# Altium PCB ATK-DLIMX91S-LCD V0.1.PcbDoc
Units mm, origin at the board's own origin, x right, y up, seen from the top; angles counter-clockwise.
Board outline 43.25 x 70.25 mm, 2 copper layers (Top Layer, Bottom Layer), stack 1.495 mm thick; 16 components, 39 nets, 110 pads, 307 vias.
Unrouted connection lines stored in the file: 5.
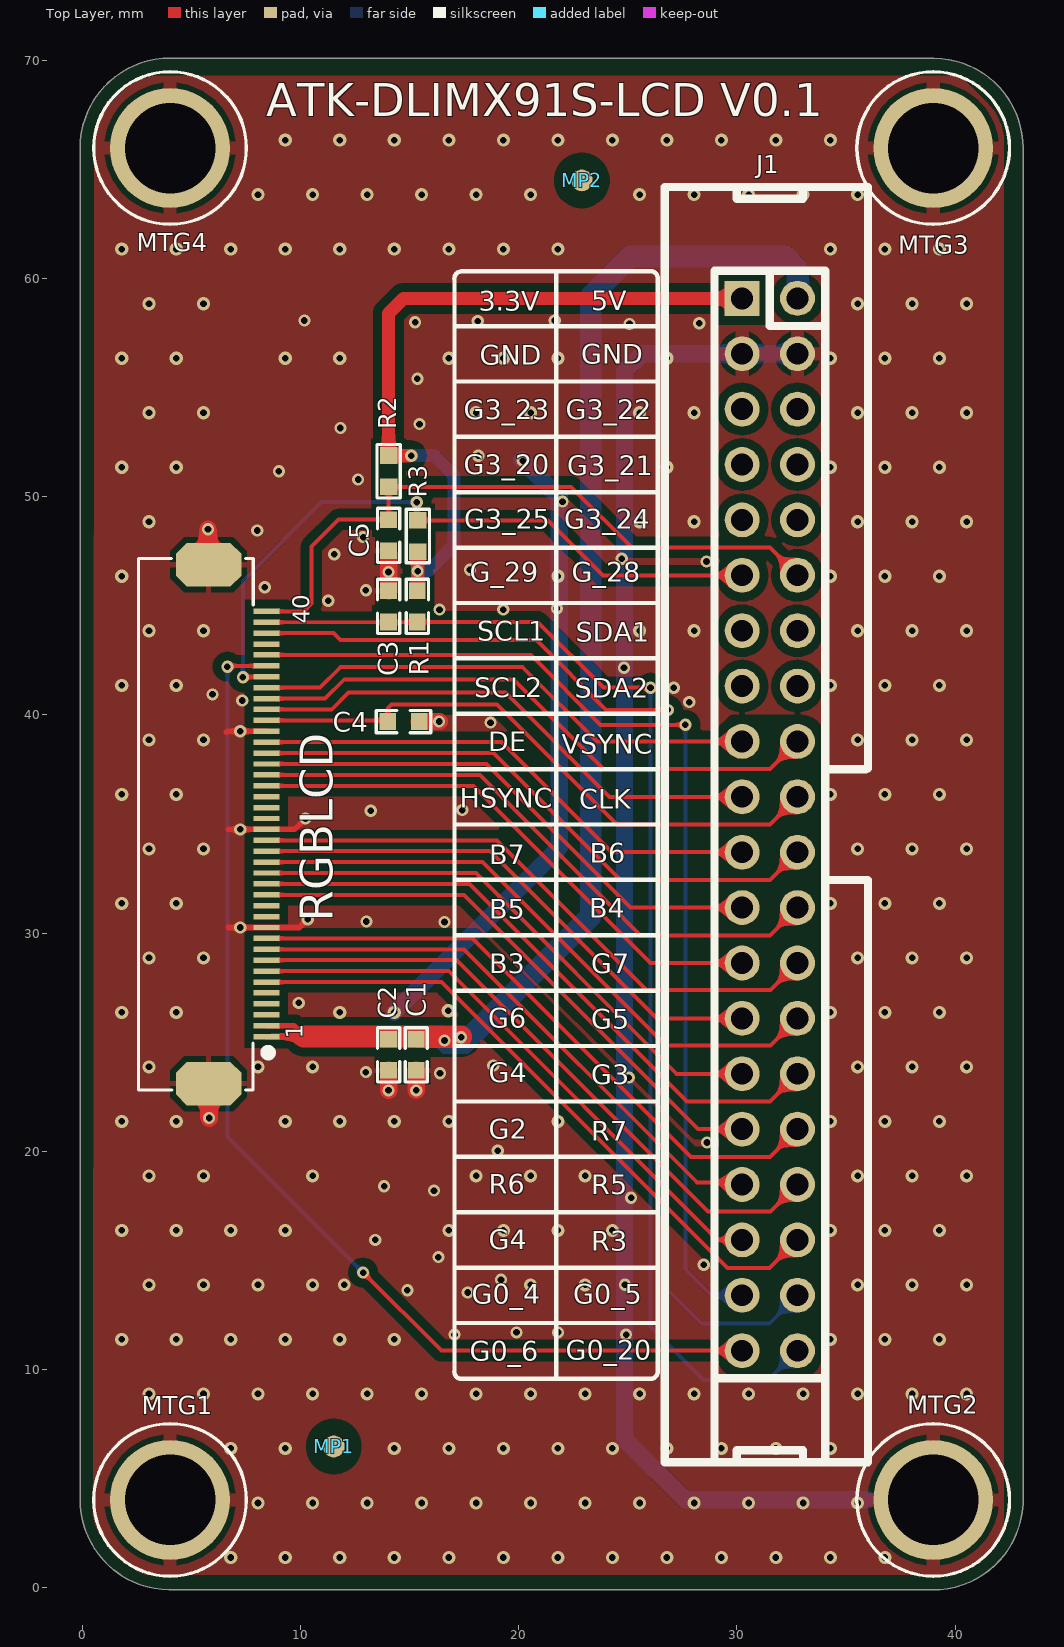
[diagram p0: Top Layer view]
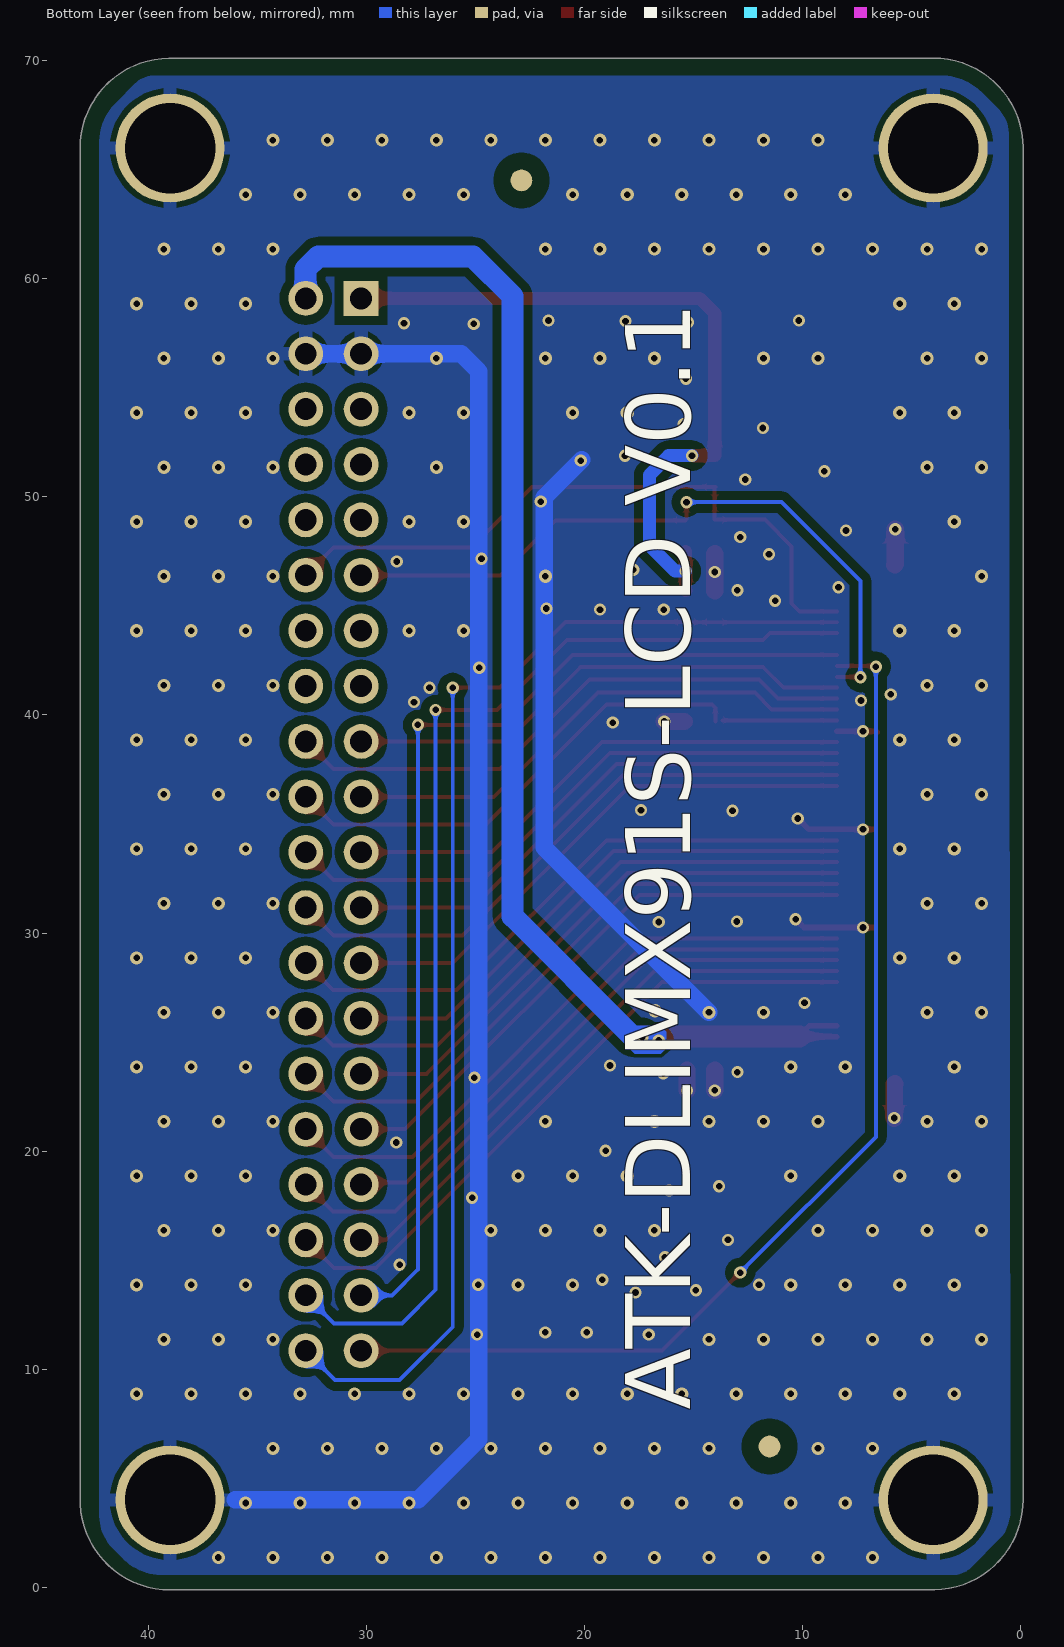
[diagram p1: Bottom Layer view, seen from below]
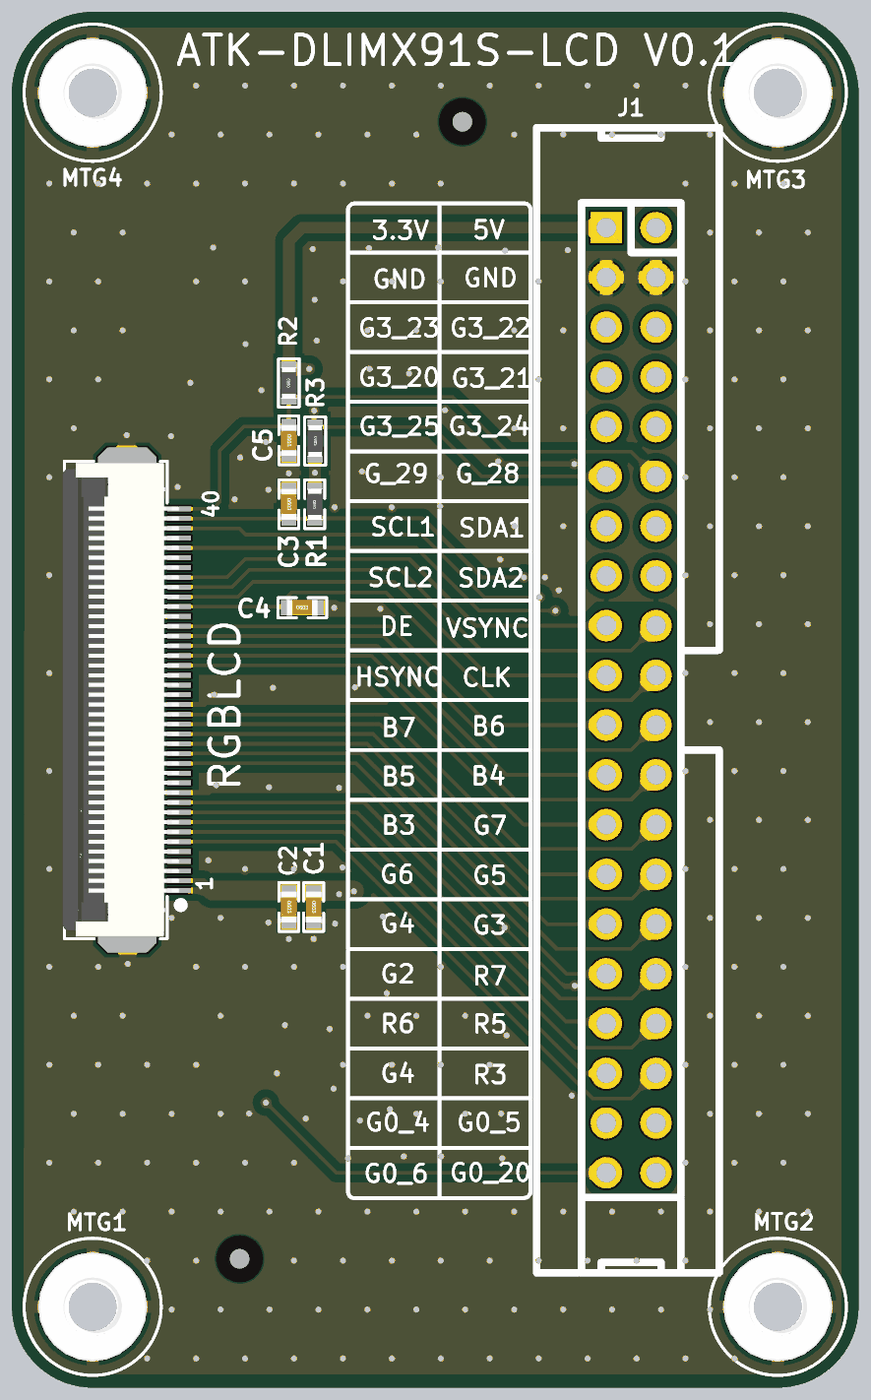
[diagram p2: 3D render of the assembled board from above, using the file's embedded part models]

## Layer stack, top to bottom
Top Solder: solder mask 0.0102, Solder Resist, Dk 3.5
Top Layer: signal copper 0.0175
Dielectric 2: prepreg 0.13, PP-006, Dk 4.1
Dielectric 1: dielectric 1.2, FR-4, Dk 4.8
Dielectric 3: prepreg 0.13, PP-006, Dk 4.1
Bottom Layer: signal copper 0.0175
Bottom Solder: solder mask 0.0102, Solder Resist, Dk 3.5

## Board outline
-0.123,4.022 ccw(c4.004,4.004) 3.954,-0.123 3.988,-0.127 38.946,-0.127 38.978,-0.123 ccw(c38.996,4.004) 43.118,3.797 43.127,3.846 43.127,65.946 43.123,65.996 ccw(c38.996,65.996) 39.046,70.123 39.012,70.127 4,70.127 ccw(c4,66) -0.127,66.02 -0.127,66.016

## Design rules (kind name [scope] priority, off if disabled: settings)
BoardOutlineClearance [All] p1: gap=0.508 ignorepadtopadclearanceinfootprint=FALSE
Clearance [All] p1: gap=0.152 ignorepadtopadclearanceinfootprint=FALSE except(0.14: Arc-Arc Arc-Track Arc-SMDPad Track-SMDPad SMDPad-SMDPad; 0.203: Arc-Fill Track-Fill SMDPad-Fill THPad-Fill Via-Fill; 0.216: Track-Track; 0.381: Fill-Fill; 0.4: Arc-Poly Track-Poly SMDPad-Poly THPad-Poly Via-Poly Fill-Poly Poly-Poly)
DiffPairsRouting [InDifferentialPair('MIC')] p1: maxlimit=0.254 minlimit=0.254 mostfreqgap=0.254 toplayer_minwidth=0.254 toplayer_maxwidth=0.381 toplayer_prefwidth=0.254 bottomlayer_minwidth=0.254 bottomlayer_maxwidth=0.381 bottomlayer_prefwidth=0.254 maxuncoupledlength=12.7
DiffPairsRouting 90OHM [InDifferentialPairClass('90OHM')] p2: maxlimit=0.178 minlimit=0.178 mostfreqgap=0.178 toplayer_minwidth=0.178 toplayer_maxwidth=0.178 toplayer_prefwidth=0.178 bottomlayer_minwidth=0.178 bottomlayer_maxwidth=0.178 bottomlayer_prefwidth=0.178 maxuncoupledlength=12.7
DiffPairsRouting 100OHM [InDifferentialPairClass('100OHM')] p3: maxlimit=0.198 minlimit=0.14 mostfreqgap=0.14 toplayer_maxgap=0.14 toplayer_minwidth=0.127 toplayer_maxwidth=0.127 toplayer_prefwidth=0.127 bottomlayer_minwidth=0.127 bottomlayer_maxwidth=0.127 bottomlayer_prefwidth=0.127 maxuncoupledlength=12.7
PlaneClearance [All] p1: clearance=0.203
PlaneConnect [All] p1: planeconnectstyle=Direct reliefexpansion=0.508 reliefentries=4 reliefconductorwidth=0.508 reliefairgap=0.254
PolygonConnect [All] p1: thpad.connectstyle=Relief thpad.reliefconductorwidth=0.635 thpad.reliefentries=4 thpad.polygonreliefangle="90 Angle" thpad.airgapwidth=0.254 smdpad.connectstyle=Relief smdpad.reliefconductorwidth=0.254 smdpad.reliefentries=4 smdpad.polygonreliefangle="90 Angle" smdpad.airgapwidth=0.254 via.connectstyle=Direct via.reliefconductorwidth=0.254 via.reliefentries=4 via.polygonreliefangle="90 Angle" via.airgapwidth=0.254
RoutingVias [All] p1: holewidth=0.254 width=0.508 viastyle="Through Hole" minholewidth=0.203 minwidth=0.406 maxholewidth=2 maxwidth=2
SilkToSilkClearance [All] p1: silktosilkclearance=0.051
SilkToSolderMaskClearance [IsPad] p1: minsilkscreentomaskgap=0.051 clearancetoexposedcopper=TRUE
SolderMaskExpansion [All] p1: expansion=0.102 istentingtop=FALSE
Width 50OHM [InNetClass('50OHM')] p1: maxlimit=0.254 minlimit=0.183 preferedwidth=0.183 minimp=50.000000 maximp=50.000000 favimp=50.000000
Width [All] p2: maxlimit=2.54 minlimit=0.152 preferedwidth=0.183
25 further rules are at their usual default settings.

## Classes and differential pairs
net class RGB_LCD: GPIO3_IO22
net class GMAC: GPIO3_IO20 GPIO3_IO25 GPIO_IO01 GPIO_IO28 GPIO_IO29
net class 50OHM: GPIO3_IO20 GPIO3_IO25 GPIO_IO28 GPIO_IO29
differential pair class 90OHM: D_CPU_USB0 D_CPU_USB1 D_HUB1 D_HUB2 D_HUB3 D_HUB4 USB_OTG USB_TTL
differential pair class 100OHM: D_PHY0_RJ45_D1 D_PHY0_RJ45_D2 D_PHY0_RJ45_D3 D_PHY0_RJ45_D4 D_PHY1_RJ45_D1 D_PHY1_RJ45_D2 D_PHY1_RJ45_D3 D_PHY1_RJ45_D4
differential pair MIC: +"" -""
differential pair USB_TTL: +I2C2_SCL -I2C1_SDA
differential pair USB_OTG: +"" -""
differential pair D_CPU_USB0: +"" -""
differential pair D_CPU_USB1: +"" -""
differential pair D_HUB2: +"" -""
differential pair D_HUB1: +"" -""
differential pair D_HUB3: +"" -""
differential pair D_HUB4: +"" -""
differential pair D_PHY0_RJ45_D1: +"" -""
differential pair D_PHY0_RJ45_D2: +"" -""
differential pair D_PHY0_RJ45_D3: +"" -""
differential pair D_PHY0_RJ45_D4: +"" -""
differential pair D_PHY1_RJ45_D1: +"" -""
differential pair D_PHY1_RJ45_D2: +"" -""
differential pair D_PHY1_RJ45_D3: +"" -""
differential pair D_PHY1_RJ45_D4: +"" -""

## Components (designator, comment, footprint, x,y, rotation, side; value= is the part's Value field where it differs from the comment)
C1 "10uF" "C 0603" 15.291,24.416 r270 top
C2 "100nF" "C 0603" 14.021,24.416 r270 top
C3 "1nF" "C 0603" 14.021,44.983 r270 top
C4 "22pF" "C 0603" 14.707,39.7 r0 top
C5 "10uF" "C 0603" 14.021,48.241 r270 top
J1 "40Pin" "IDC 2.54-2*20P" 30.237,59.106 r270 top
MP1 "Mark Point" "MARK POINT" 11.506,6.452 r90 top
MP2 "Mark Point" "MARK POINT" 22.885,64.516 r90 top
MTG1 "MTG_Hole" M3-6ET 4,4 r0 top
MTG2 "MTG_Hole" M3-6ET 39,4 r0 top
MTG3 "MTG_Hole" M3-6ET 39,66 r0 top
MTG4 "MTG_Hole" M3-6ET 4,66 r0 top
R1 "10K" "R 0603"#1 15.342,44.983 r90 top
R2 "10K" "R 0603"#2 14.021,51.181 r90 top
R3 "10K" "R 0603"#2 15.367,48.209 r270 top
RGBLCD "RGBLCD" FPC0.5-TOP40P 7.095,34.99 r90 top

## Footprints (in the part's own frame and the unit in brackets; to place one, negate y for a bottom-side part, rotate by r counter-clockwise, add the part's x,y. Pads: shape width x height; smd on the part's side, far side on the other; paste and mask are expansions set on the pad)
"C 0603" [mil] "无极性贴片电容"
  rect 30x30 smd mask+2: 1(-28.25,0) 2(28.25,0)
  silkscreen extent -49,-20 49,20, body extent -31,-16 32,16, height 32
FPC0.5-TOP40P [mm] "FPCTOP;0.5mm;"
  rect 0.25x1.2 smd: 1(-9.737,-1.326) 2(-9.237,-1.326) 3(-8.737,-1.326) 4(-8.237,-1.326) 5(-7.737,-1.326) 6(-7.237,-1.326) 7(-6.737,-1.326) 8(-6.237,-1.326) 9(-5.737,-1.326) 10(-5.237,-1.326) 11(-4.737,-1.326) 12(-4.237,-1.326) 13(-3.737,-1.326) 14(-3.237,-1.326) 15(-2.737,-1.326) 16(-2.237,-1.326) 17(-1.737,-1.326) 18(-1.237,-1.326) 19(-0.737,-1.326) 20(-0.237,-1.326) 21(0.263,-1.326) 22(0.763,-1.326) 23(1.263,-1.326) 24(1.763,-1.326) 25(2.263,-1.326) 26(2.763,-1.326) 27(3.263,-1.326) 28(3.763,-1.326) 29(4.263,-1.326) 30(4.763,-1.326) 31(5.263,-1.326) 32(5.763,-1.326) 33(6.263,-1.326) 34(6.763,-1.326) 35(7.263,-1.326) 36(7.763,-1.326) 37(8.263,-1.326) 38(8.763,-1.326) 39(9.263,-1.326) 40(9.763,-1.326)
  oct 2x3 smd: A(-11.9,1.326) B(11.9,1.326)
  silkscreen extent -12.19,-1.58 12.19,4.54, body extent -12.08,-1.35 12.12,4.65, height 2
"IDC 2.54-2*20P" [mm]
  rect 1.6x1.6 hole 1: 1(0,0)
  round 1.6 hole 1: 2(0,2.54) 3(2.54,0) 4(2.54,2.54) 5(5.08,0) 6(5.08,2.54) 7(7.62,0) 8(7.62,2.54) 9(10.16,0) 10(10.16,2.54) 11(12.7,0) 12(12.7,2.54) 13(15.24,0) 14(15.24,2.54) 15(17.78,0) 16(17.78,2.54) 17(20.32,0) 18(20.32,2.54) 19(22.86,0) 20(22.86,2.54) 21(25.4,0) 22(25.4,2.54) 23(27.94,0) 24(27.94,2.54) 25(30.48,0) 26(30.48,2.54) 27(33.02,0) 28(33.02,2.54) 29(35.56,0) 30(35.56,2.54) 31(38.1,0) 32(38.1,2.54) 33(40.64,0) 34(40.64,2.54) 35(43.18,0) 36(43.18,2.54) 37(45.72,0) 38(45.72,2.54) 39(48.26,0) 40(48.26,2.54)
  silkscreen extent -5.11,-3.56 53.37,5.77
M3-6ET [mm]
  round 5.5 / inner round 5 / far side round 5 hole 4.15 mask+0.051: 1(0,0)
  silkscreen extent -3.5,-3.5 3.5,3.5, body extent -2.77,-2.78 2.77,2.78, height 6.03
"MARK POINT" [mm]
  round 1 smd: 1(0,0)
  round 2.4 on Top Solder paste+0 mask+0.01: 1(0,0)
  round 2.4 on Bottom Solder paste+0 mask+0.01: 1(0,0)
  round 1 smd far side: 1_1(0,0)
  Top Layer pour cut-out: -1.27,0.125 -1.221,0.37 -1.125,0.602 -0.986,0.81 -0.81,0.986 -0.602,1.125 -0.37,1.221 -0.125,1.27 0,1.27 0.125,1.27 0.37,1.221 0.602,1.125 0.81,0.986 0.986,0.81 1.125,0.602 1.221,0.37 1.27,0.125 1.27,0 1.27,0 1.27,-0.125 1.221,-0.37 1.125,-0.602 0.986,-0.81 0.81,-0.986 0.602,-1.125 0.37,-1.221 0.125,-1.27 0,-1.27 0,-1.27 -0.125,-1.27 -0.37,-1.221 -0.602,-1.125 -0.81,-0.986 -0.986,-0.81 -1.125,-0.602 -1.221,-0.37 -1.27,-0.125 -1.27,0
  Bottom Layer pour cut-out: -1.27,0 -1.27,0.125 -1.221,0.37 -1.125,0.602 -0.986,0.81 -0.81,0.986 -0.602,1.125 -0.37,1.221 -0.125,1.27 0,1.27 0,1.27 0.125,1.27 0.37,1.221 0.602,1.125 0.81,0.986 0.986,0.81 1.125,0.602 1.221,0.37 1.27,0.125 1.27,0 1.27,0 1.27,-0.125 1.221,-0.37 1.125,-0.602 0.986,-0.81 0.81,-0.986 0.602,-1.125 0.37,-1.221 0.125,-1.27 0,-1.27 0,-1.27 -0.125,-1.27 -0.37,-1.221 -0.602,-1.125 -0.81,-0.986 -0.986,-0.81 -1.125,-0.602 -1.221,-0.37 -1.27,-0.125 -1.27,0
"R 0603"#1 [mil] "1/10W贴片电阻"
  rect 30x30 smd mask+2: 1(-28.25,0) 2(28.25,0)
  silkscreen extent -49,-20 49,20, body extent -32,-16 31,16, height 16
"R 0603"#2 [mil] "1/10W贴片电阻"
  rect 30x31.5 smd mask+2: 1(-28.25,0) 2(28.25,0)
  silkscreen extent -48,-21 48,21, body extent -32,-16 31,16, height 16

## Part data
C1 C2 C3 C4 C5: library part C, "无极性贴片电容"
J1: library part RPI40Pin
MP1 MP2: library part MARK
MTG1 MTG2 MTG3 MTG4: "螺丝孔"
R1 R2 R3: library part R
RGBLCD: library part FPC-40, "FPC-40P-0.5mm"

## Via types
v1: diameter 0.6, hole 0.3, Top Layer to Bottom Layer, tented both sides, 227 vias
v2: diameter 0.559, hole 0.305, Top Layer to Bottom Layer, tented both sides, 80 vias

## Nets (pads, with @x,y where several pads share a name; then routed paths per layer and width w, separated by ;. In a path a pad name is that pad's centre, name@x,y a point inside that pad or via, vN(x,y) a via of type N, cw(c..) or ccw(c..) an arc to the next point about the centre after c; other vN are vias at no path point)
GND: C1.2 C2.2 C3.1 C4.2 C5.2 J1.3 J1.4 MTG1.1 MTG2.1 MTG3.1 MTG4.1 RGBLCD.11 RGBLCD.20 RGBLCD.29 RGBLCD.A RGBLCD.B | length 115.8
  Top Layer w0.254: 6.579,39.218 cw(c6.663,39.133) 6.663,39.253 RGBLCD.29 ; 6.663,30.253 RGBLCD.11 9.933,30.253 v2(10.312,30.632) ; 6.663,34.753 RGBLCD.20 9.708,34.753 v2(10.211,35.255)
  Top Layer w0.8: v2(5.74,48.514) 5.74,46.918 RGBLCD.B ; RGBLCD.A 5.791,23.068 v2(5.791,21.514) ; v2(14.021,22.784) C2.2 ; C3.1 C5.2@14.021,47.39 ; v2(15.291,22.784) C1.2 ; C4.2 v2(16.339,39.7)
  Bottom Layer w0.8: v1(14.284,26.361) 21.844,33.921 21.844,44.882 21.844,46.361 21.844,49.987 v2@20.125,51.706 ; J1.4 25.654,56.566 24.841,55.753 24.841,6.782 27.623,4 36,4
  other v1: 6.784,1.361 9.284,1.361 11.784,1.361 14.284,1.361 16.784,1.361 19.284,1.361 21.784,1.361 24.284,1.361 26.784,1.361 29.284,1.361 31.784,1.361 34.284,1.361 36.784,1.361 8.034,3.861 10.534,3.861 13.034,3.861 15.534,3.861 18.034,3.861 20.534,3.861 23.034,3.861 25.534,3.861 28.034,3.861 30.534,3.861 33.034,3.861 35.534,3.861 6.784,6.361 9.284,6.361 14.284,6.361 16.784,6.361 19.284,6.361 21.784,6.361 24.284,6.361 26.784,6.361 29.284,6.361 31.784,6.361 34.284,6.361 3.034,8.861 5.534,8.861 8.034,8.861 10.534,8.861 13.034,8.861 15.534,8.861 18.034,8.861 20.534,8.861 23.034,8.861 25.534,8.861 28.034,8.861 30.534,8.861 33.034,8.861 35.534,8.861 38.034,8.861 40.534,8.861 1.784,11.361 4.284,11.361 6.784,11.361 9.284,11.361 11.784,11.361 14.284,11.361 34.284,11.361 36.784,11.361 39.284,11.361 3.034,13.861 5.534,13.861 8.034,13.861 10.534,13.861 20.534,13.861 23.034,13.861 35.534,13.861 38.034,13.861 40.534,13.861 1.784,16.361 4.284,16.361 6.784,16.361 9.284,16.361 16.784,16.361 19.284,16.361 21.784,16.361 24.284,16.361 34.284,16.361 36.784,16.361 39.284,16.361 3.034,18.861 5.534,18.861 10.534,18.861 18.034,18.861 20.534,18.861 23.034,18.861 35.534,18.861 38.034,18.861 40.534,18.861 1.784,21.361 4.284,21.361 9.284,21.361 11.784,21.361 14.284,21.361 16.784,21.361 21.784,21.361 34.284,21.361 36.784,21.361 39.284,21.361 3.034,23.861 8.034,23.861 10.534,23.861 35.534,23.861 38.034,23.861 40.534,23.861 1.784,26.361 4.284,26.361 11.784,26.361 34.284,26.361 36.784,26.361 39.284,26.361 16.76,26.436 3.034,28.861 5.534,28.861 35.534,28.861 38.034,28.861 40.534,28.861 1.784,31.361 4.284,31.361 34.284,31.361 36.784,31.361 39.284,31.361 3.034,33.861 5.534,33.861 35.534,33.861 38.034,33.861 40.534,33.861 1.784,36.361 4.284,36.361 34.284,36.361 36.784,36.361 39.284,36.361 3.034,38.861 5.534,38.861 35.534,38.861 38.034,38.861 40.534,38.861 1.784,41.361 4.284,41.361 34.284,41.361 36.784,41.361 39.284,41.361 3.034,43.861 5.534,43.861 25.534,43.861 28.034,43.861 35.534,43.861 38.034,43.861 40.534,43.861 1.784,46.361 21.784,46.361 34.284,46.361 36.784,46.361 39.284,46.361 3.034,48.861 25.534,48.861 28.034,48.861 35.534,48.861 38.034,48.861 40.534,48.861 1.784,51.361 4.284,51.361 26.784,51.361 34.284,51.361 36.784,51.361 39.284,51.361 3.034,53.861 5.534,53.861 18.034,53.861 20.534,53.861 25.534,53.861 28.034,53.861 35.534,53.861 38.034,53.861 40.534,53.861 1.784,56.361 4.284,56.361 9.284,56.361 11.784,56.361 16.784,56.361 19.284,56.361 21.784,56.361 26.784,56.361 34.284,56.361 36.784,56.361 39.284,56.361 3.034,58.861 5.534,58.861 35.534,58.861 38.034,58.861 40.534,58.861 1.784,61.361 4.284,61.361 6.784,61.361 9.284,61.361 11.784,61.361 14.284,61.361 16.784,61.361 19.284,61.361 21.784,61.361 34.284,61.361 36.784,61.361 39.284,61.361 8.034,63.861 10.534,63.861 13.034,63.861 15.534,63.861 18.034,63.861 20.534,63.861 25.534,63.861 28.034,63.861 30.534,63.861 33.034,63.861 35.534,63.861 9.284,66.361 11.784,66.361 14.284,66.361 16.784,66.361 19.284,66.361 21.784,66.361 24.284,66.361 26.784,66.361 29.284,66.361 31.784,66.361 34.284,66.361
  other v2: 17.043,11.582 24.917,11.582 19.888,11.684 21.793,11.684 17.653,13.513 14.884,13.614 11.989,13.868 24.867,13.868 19.177,14.097 28.473,14.783 16.307,15.138 13.411,15.926 25.146,17.856 16.104,18.186 13.818,18.39 19.025,20.015 28.626,20.396 25.044,23.368 16.383,23.571 12.979,23.622 18.821,23.927 9.906,26.797 7.219,30.253 16.586,30.505 13.005,30.531 7.219,34.753 13.208,35.611 17.399,35.636 7.219,39.253 18.694,39.649 27.813,40.589 7.315,40.665 5.944,40.945 27.102,41.25 24.816,42.164 16.358,44.831 19.279,44.831 21.742,44.882 11.252,45.237 12.979,45.72 8.342,45.861 14.021,46.558 17.755,46.66 28.6,47.041 24.714,47.168 11.532,47.371 12.852,48.158 8.001,48.463 21.996,49.784 12.624,50.8 8.992,51.181 20.168,51.664 18.136,51.892 11.811,53.162 15.443,53.34 15.342,55.423 25.07,57.937 28.27,57.963 15.24,58.014 18.11,58.064 10.16,58.09 21.641,58.09
GPIO3_IO20: J1.7
GPIO3_IO21: J1.8
GPIO3_IO22: J1.6
GPIO3_IO23: J1.5
GPIO3_IO24: J1.10
GPIO3_IO25: J1.9
GPIO_IO00: C4.1 J1.20 RGBLCD.30 | length 27.5
  Top Layer w0.183: RGBLCD.30 C4.1@13.66,39.753 ; C4.1 13.989,40.329 14.148,40.488 18.991,40.488 24.503,34.976 31.507,34.976 J1.20
GPIO_IO01: J1.17 RGBLCD.33 | length 23.6
  Top Layer w0.183: RGBLCD.33 10.874,41.253 11.811,42.189 20.168,42.189 23.571,38.786 J1.17
GPIO_IO02: J1.18 RGBLCD.32 | length 26.9
  Top Layer w0.183: RGBLCD.32 11.111,40.753 11.989,41.631 19.761,41.631 23.876,37.516 31.507,37.516 J1.18
GPIO_IO03: J1.19 RGBLCD.31 | length 24.1
  Top Layer w0.183: RGBLCD.31 11.415,40.253 12.184,41.021 19.38,41.021 24.155,36.246 J1.19
GPIO_IO04: J1.37 RGBLCD.36 | length 48.6
  Top Layer w0.183: RGBLCD.36 20.544,42.753 23.749,39.548 v2(27.635,39.548)
  Bottom Layer w0.183: v2(27.635,39.548) 27.635,14.58 28.829,13.386 J1.37
GPIO_IO05: J1.38 RGBLCD.38 | length 53.6
  Top Layer w0.183: RGBLCD.38 11.492,43.753 11.811,43.434 20.803,43.434 24.003,40.234 v2(26.822,40.234)
  Bottom Layer w0.183: v2(26.822,40.234) 26.822,13.64 28.372,12.09 31.481,12.09 J1.38
GPIO_IO06: J1.39 RGBLCD.35 | length 51
  Top Layer w0.183: v2(6.629,42.215) 6.667,42.253 RGBLCD.35 ; v2@12.852,14.44 16.447,10.846 J1.39
  Bottom Layer w0.183: v2(6.629,42.215) 6.629,20.65 v2(12.852,14.427)
GPIO_IO07: J1.36 RGBLCD.6 | length 30.3
  Top Layer w0.183: RGBLCD.6 16.443,27.753 29.566,14.63 31.481,14.63 J1.36
GPIO_IO08: J1.35 RGBLCD.7 | length 26.9
  Top Layer w0.183: RGBLCD.7 16.782,28.253 29.108,15.926 J1.35
GPIO_IO09: J1.34 RGBLCD.8 | length 29.6
  Top Layer w0.183: RGBLCD.8 17.145,28.753 28.677,17.221 31.532,17.221 J1.34
GPIO_IO10: J1.33 RGBLCD.9 | length 26.3
  Top Layer w0.183: RGBLCD.9 17.483,29.253 28.167,18.569 30.133,18.569 J1.33
GPIO_IO11: J1.32 RGBLCD.10 | length 29
  Top Layer w0.183: RGBLCD.10 17.872,29.753 27.889,19.736 31.507,19.736 J1.32
GPIO_IO14: J1.31 RGBLCD.14 | length 26.3
  Top Layer w0.183: RGBLCD.14 17.473,31.753 28.219,21.006 J1.31
GPIO_IO15: J1.30 RGBLCD.15 | length 29
  Top Layer w0.183: RGBLCD.15 17.735,32.253 27.711,22.276 31.507,22.276 J1.30
GPIO_IO16: J1.29 RGBLCD.16 | length 25.6
  Top Layer w0.183: RGBLCD.16 18.022,32.753 27.229,23.546 J1.29
GPIO_IO17: J1.28 RGBLCD.17 | length 28.4
  Top Layer w0.183: RGBLCD.17 18.335,33.253 26.746,24.841 31.532,24.841 J1.28
GPIO_IO18: J1.27 RGBLCD.18 | length 25
  Top Layer w0.183: RGBLCD.18 18.673,33.753 26.34,26.086 J1.27
GPIO_IO19: J1.26 RGBLCD.19 | length 27.7
  Top Layer w0.183: RGBLCD.19 18.986,34.253 25.857,27.381 31.532,27.381 J1.26
GPIO_IO20: C3.2 J1.40 R1.1 RGBLCD.39 | length 56.5
  Top Layer w0.183: RGBLCD.39 14.046,44.253 15.328,44.253 R1.1 20.86,44.266 23.876,41.25 v2(26.035,41.25)
  Bottom Layer w0.183: v2(26.035,41.25) 26.035,11.938 28.473,9.5 31.431,9.5 J1.40
GPIO_IO23: J1.25 RGBLCD.24 | length 25.2
  Top Layer w0.183: RGBLCD.24 17.908,36.753 26.035,28.626 J1.25
GPIO_IO24: J1.24 RGBLCD.25 | length 27.9
  Top Layer w0.183: RGBLCD.25 18.221,37.253 25.578,29.896 31.507,29.896 J1.24
GPIO_IO25: J1.23 RGBLCD.26 | length 24.5
  Top Layer w0.183: RGBLCD.26 18.521,37.753 25.108,31.166 J1.23
GPIO_IO26: J1.22 RGBLCD.27 | length 27.3
  Top Layer w0.183: RGBLCD.27 18.834,38.253 24.651,32.436 31.507,32.436 J1.22
GPIO_IO27: J1.21 RGBLCD.28 | length 23.9
  Top Layer w0.183: RGBLCD.28 19.198,38.753 24.245,33.706 J1.21
GPIO_IO28: C5.1 J1.12 R2.1 RGBLCD.40 | length 30.9
  Top Layer w0.183: RGBLCD.40 10.132,44.753 10.49,45.11 10.49,47.727 11.722,48.959 C5.1 14.021,50.438 13.995,50.463 22.397,50.463 25.185,47.676 31.507,47.676 J1.12
GPIO_IO29: J1.11 R3.1 RGBLCD.34 | length 31.7
  Top Layer w0.183: v2(7.341,41.729) 7.352,41.741 8.41,41.741 RGBLCD.34 ; v2(15.316,49.759) 15.316,48.978 R3.1 21.33,48.927 23.851,46.406 J1.11
  Bottom Layer w0.183: v2(7.341,41.729) 7.341,46.152 10.947,49.759 v2(15.316,49.759)
I2C1_SCL: J1.13
I2C1_SDA: J1.14
I2C2_SCL: J1.15
I2C2_SDA: J1.16
VCC_3V3: J1.1 R1.2 R2.2 R3.2 | length 33.6
  Top Layer w0.6: v2(15.062,51.892) 14.027,51.892 R2.2 14.021,58.415 14.711,59.106 J1.1 ; R1.2 15.354,45.714 v2(15.354,46.596) 15.354,47.479 R3.2
  Bottom Layer w0.6: v2(15.062,51.892) 16.129,51.892 17.018,51.003 17.018,47.777 15.837,46.596 v2(15.354,46.596)
VCC_5V: C1.1 C2.1 J1.2 RGBLCD.1 RGBLCD.2 | length 61.4
  Top Layer w0.254: RGBLCD.1 10.129,25.253 10.129,25.304 9.68,25.753 RGBLCD.2
  Top Layer w1: 10.129,25.253 14.021,25.253 15.291,25.253 v2@17.348,25.253 ; C1.1@15.381,25.223 v2(17.348,25.222)
  Bottom Layer w1: v2(17.348,25.222) 17.755,25.222 23.292,30.759 23.292,59.207 25.11,61.026 32.206,61.026 32.791,60.44 32.791,59.12 J1.2
  other v2: 16.586,25.07
pads on no net: MP1.1 MP1.1_1 MP2.1 MP2.1_1 RGBLCD.3 RGBLCD.4 RGBLCD.5 RGBLCD.12 RGBLCD.13 RGBLCD.21 RGBLCD.22 RGBLCD.23 RGBLCD.37

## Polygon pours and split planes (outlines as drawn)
GND on Bottom Layer "GND_L02_P000" (solid, remove dead copper, pour order 0): 0.478,4.717 ccw(c0.521,4.675) 0.46,4.675 0.46,3.319 ccw(c1.884,3.319) 0.877,2.312 2.357,0.832 ccw(c3.017,1.492) 3.017,0.559 39.357,0.559 ccw(c39.357,3.099) 41.153,1.303 41.6,1.749 ccw(c40.053,3.295) 42.24,3.295 42.24,66.258 ccw(c39.7,66.258) 41.496,68.054 40.589,68.961 ccw(c39.731,68.103) 39.731,69.317 3.592,69.317 ccw(c3.592,66.777) 1.796,68.573 1.041,67.818 ccw(c2.268,66.592) 0.533,66.592 0.533,62.763
GND on Top Layer "GND_L01_P001" (solid, remove dead copper, pour order 1): 0.478,4.717 ccw(c0.521,4.675) 0.46,4.675 0.46,3.319 ccw(c1.884,3.319) 0.877,2.312 2.357,0.832 ccw(c3.017,1.492) 3.017,0.559 39.357,0.559 ccw(c39.357,3.099) 41.153,1.303 41.6,1.749 ccw(c40.053,3.295) 42.24,3.295 42.24,66.258 ccw(c39.7,66.258) 41.496,68.054 40.589,68.961 ccw(c39.731,68.103) 39.731,69.317 3.592,69.317 ccw(c3.592,66.777) 1.796,68.573 1.041,67.818 ccw(c2.268,66.592) 0.533,66.592 0.533,62.763

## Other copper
Top Layer:
  pour cut-out: 28.956,39.192 cw(c29.14,39.192) 29.01,39.322 29.616,39.929 cw(c29.8,39.745) 29.8,40.005 32.898,40.005 cw(c32.898,38.791) 33.757,39.649 cw(c33.511,39.404) 33.858,39.404 33.858,10.494 cw(c32.991,10.494) 33.604,9.881 cw(c33.052,10.432) 33.052,9.652 29.965,9.652 cw(c29.965,10.432) 29.413,9.881 cw(c30.088,10.555) 29.134,10.555 29.134,38.437 ccw(c28.353,38.437) 28.905,38.989
Bottom Layer:
  region net VCC_5V: 18.275,25.754 18.274,25.756 16.524,25.756 16.245,25.476 16.245,24.714 16.499,24.46 17.692,24.46 18.378,25.146 18.378,25.656 18.277,25.756

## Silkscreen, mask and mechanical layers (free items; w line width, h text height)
Top Overlay:
  lines w0.2: 17.043,9.838 17.043,19.472 17.043,19.726 17.043,60.053 ; 17.043,12.116 26.365,12.116 ; 17.043,14.656 26.365,14.656 ; 17.043,17.196 26.365,17.196 ; 17.043,19.736 26.365,19.736 ; 17.043,22.276 26.365,22.276 ; 17.043,24.816 26.365,24.816 ; 17.043,27.356 26.365,27.356 ; 17.043,29.896 26.365,29.896 ; 17.043,32.436 26.365,32.436 ; 17.043,34.976 26.365,34.976 ; 17.043,37.516 26.365,37.516 ; 17.043,40.056 26.365,40.056 ; 17.043,42.596 26.365,42.596 ; 17.043,45.136 26.365,45.136 ; 17.043,47.676 26.365,47.676 ; 17.043,50.216 26.365,50.216 ; 17.043,52.756 26.365,52.756 ; 17.043,55.296 26.365,55.296 ; 17.043,57.836 26.365,57.836 ; 17.348,9.56 26.06,9.56 ; 17.348,60.35 26.06,60.35 ; 21.717,9.627 21.717,60.325 ; 26.365,9.848 26.365,19.482 26.365,19.736 ; 26.365,60.063 26.365,19.736
  lines w0.203: 17.042,9.881 ccw(c17.362,9.871) 17.348,9.55 ; 17.042,60.01 cw(c17.362,60.02) 17.348,60.34 ; 26.06,9.561 ccw(c26.046,9.881) 26.367,9.891 ; 26.06,60.35 cw(c26.046,60.03) 26.367,60.02
  text "ATK-DLIMX91S-LCD V0.1" at 8.414,67.449 h1.5
  text "5V" at 23.315,58.57 h0.9
  text "3.3V" at 18.159,58.545 h0.9
  text "GND" at 22.857,56.114 h0.9
  text "GND" at 18.207,56.051 h0.9
  text "G3_23" at 17.473,53.561 h0.9
  text "G3_22" at 22.146,53.559 h0.9
  text "G3_20" at 17.473,51.047 h0.9
  text "G3_21" at 22.22,50.996 h0.9
  text "G3_25" at 17.493,48.545 h0.9
  text "G3_24" at 22.07,48.545 h0.9
  text "G_29" at 17.752,46.119 h0.9
  text "G_28" at 22.426,46.119 h0.9
  text "SCL1" at 18.09,43.394 h0.9
  text "SDA1" at 22.604,43.355 h0.9
  text "SCL2" at 17.955,40.813 h0.9
  text "SDA2" at 22.553,40.79 h0.9
  text "DE" at 18.583,38.326 h0.9
  text "VSYNC" at 21.956,38.232 h0.9
  text "HSYNC" at 17.295,35.735 h0.9
  text "CLK" at 22.774,35.71 h0.9
  text "B6" at 23.251,33.231 h0.9
  text "B7" at 18.649,33.158 h0.9
  text "B4" at 23.226,30.691 h0.9
  text "B5" at 18.649,30.658 h0.9
  text "B3" at 18.649,28.166 h0.9
  text "G7" at 23.317,28.154 h0.9
  text "G6" at 18.583,25.659 h0.9
  text "G5" at 23.309,25.601 h0.9
  text "G4" at 18.605,23.145 h0.9
  text "G3" at 23.309,23.061 h0.9
  text "G2" at 18.606,20.572 h0.9
  text "R7" at 23.309,20.468 h0.9
  text "R6" at 18.606,18.032 h0.9
  text "R5" at 23.32,18.009 h0.9
  text "G4" at 18.606,15.492 h0.9
  text "R3" at 23.32,15.426 h0.9
  text "G0_4" at 17.828,12.998 h0.9
  text "G0_5" at 22.502,12.998 h0.9
  text "G0_20" at 22.146,10.432 h0.9
  text "G0_6" at 17.752,10.381 h0.9
Bottom Overlay:
  text "ATK-DLIMX91S-LCD V0.1" at 15.137,8.142 h3 r270
Drill Guide:
  lines w0.254: 0,1.651 0,0 1.651,0
Mechanical 1:
  lines w0.254: 0,4.054 0,66.016 cw(c4,66) 4.05,70 ; 0.005,4.054 ccw(c4.004,4.004) 3.988,0.004 ; 3.988,0 38.946,0 ; 4,70 39.012,70 ; 38.946,0.005 ccw(c38.996,4.004) 42.996,3.988 ; 39.012,69.996 cw(c38.996,65.996) 42.995,65.946 ; 43,3.846 43,65.946
Mechanical 3:
  lines w0.013: 61.642,12.626 61.642,41.27 ; 64.792,9.426 98.542,9.426 ; 64.892,44.426 98.642,44.426 ; 101.642,12.626 101.642,41.312
Mechanical 6:
  circle w0.013: c62.03,11.426 r1.1
  circle w0.013: c62.03,42.426 r1.1
  circle w0.013: c98.03,42.426 r1.1
  circle w0.013: c98.03,11.426 r1.1
  lines w0.013: 60.03,11.426 ccw(c62.03,11.426) 62.03,9.426 98.03,9.426 ccw(c98.03,11.426) 100.03,11.426 100.03,42.426 ccw(c98.03,42.426) 98.03,44.426 62.03,44.426 ccw(c62.03,42.426) 60.03,42.426 60.03,11.426
Mechanical 14:
  circle w0.013: c85.05,10.868 r0.125
  circle w0.013: c77.591,40.307 r0.076
  circle w0.013: c89.241,39.807 r0.076
  circle w0.013: c85.291,39.807 r0.076
  lines w0.013: 60.63,19.175 60.88,19.175 ; 60.63,21.675 60.88,21.675 ; 60.63,24.175 60.88,24.175 ; 60.63,26.675 60.88,26.675 ; 60.63,29.175 60.88,29.175 ; 60.63,31.675 60.88,31.675 ; 60.63,34.175 60.88,34.175 ; 60.63,36.675 60.88,36.675 ; 62.13,16.676 62.13,15.826 62.63,15.326 65.93,15.326 65.93,16.676 ; 62.13,37.176 62.13,38.026 62.63,38.526 65.93,38.526 ; 65.93,37.176 65.93,38.526 ; 67.155,17.175 67.405,17.175 ; 67.155,19.675 67.405,19.675 ; 67.155,22.175 67.405,22.175 ; 67.155,24.675 67.405,24.675 ; 67.155,27.175 67.405,27.175 ; 67.155,29.675 67.405,29.675 ; 67.155,32.175 67.405,32.175 ; 67.155,34.675 67.405,34.675 ; 67.155,36.676 67.405,36.676 ; 77.644,21.469 76.685,21.469 76.685,22.485 77.644,22.485 ; 78.228,21.469 79.174,21.469 79.174,22.485 78.228,22.485 ; 81.801,12.421 81.801,13.321 82.601,13.321 ; 83.869,34.044 82.91,34.044 82.91,35.06 83.869,35.06 ; 84.001,13.321 84.801,13.321 84.801,12.421 ; 84.127,22.928 83.181,22.928 83.181,23.944 84.127,23.944 ; 84.14,25.697 83.181,25.697 83.181,26.713 84.14,26.713 ; 84.453,34.044 85.399,34.044 85.399,35.06 84.453,35.06 ; 84.711,22.928 85.67,22.928 85.67,23.944 84.711,23.944 ; 84.724,25.697 85.67,25.697 85.67,26.713 84.724,26.713 ; 85.226,11.694 85.226,10.736 86.242,10.736 86.242,11.694 ; 85.226,12.279 85.226,13.225 86.242,13.225 86.242,12.279 ; 86.463,34.044 85.504,34.044 85.504,35.06 86.463,35.06 ; 87.047,34.044 87.993,34.044 87.993,35.06 87.047,35.06 ; 87.192,11.694 87.192,10.736 88.208,10.736 88.208,11.694 ; 87.192,12.279 87.192,13.225 88.208,13.225 88.208,12.279 ; 89.053,34.044 88.107,34.044 88.107,35.06 89.053,35.06 ; 89.158,11.694 89.158,10.736 90.174,10.736 90.174,11.694 ; 89.158,12.279 89.158,13.225 90.174,13.225 90.174,12.279 ; 89.637,34.044 90.596,34.044 90.596,35.06 89.637,35.06 ; 92.63,19.175 92.88,19.175 ; 92.63,21.675 92.88,21.675 ; 92.63,24.175 92.88,24.175 ; 92.63,26.675 92.88,26.675 ; 92.63,29.175 92.88,29.175 ; 92.63,31.675 92.88,31.675 ; 92.63,34.175 92.88,34.175 ; 92.63,36.675 92.88,36.675 ; 94.13,16.676 94.13,15.826 94.63,15.326 97.93,15.326 97.93,16.676 ; 94.13,37.176 94.13,38.026 94.63,38.526 97.93,38.526 97.93,37.176 ; 99.155,17.175 99.405,17.175 ; 99.155,19.675 99.405,19.675 ; 99.155,22.175 99.405,22.175 ; 99.155,24.675 99.405,24.675 ; 99.155,27.175 99.405,27.175 ; 99.155,29.675 99.405,29.675 ; 99.155,32.175 99.405,32.175 ; 99.155,34.675 99.405,34.675 ; 99.155,36.676 99.405,36.676 ; 78.023,40.434 78.023,42.517 78.937,42.517 78.937,40.434 78.023,40.434 ; 85.723,39.934 86.637,39.934 86.637,42.017 85.723,42.017 85.723,39.934 ; 89.673,39.934 90.587,39.934 90.587,42.017 89.673,42.017 89.673,39.934
  text "A" at 66.039,39.181 h0.89
  text "B" at 97.939,39.081 h0.89
  text "80" at 62.375,37.704 h0.85 r90
  text "1" at 101.474,37.566 h0.85 r90
  text "80" at 94.037,37.132 h0.85 r90
  text "1" at 69.767,36.776 h0.85 r90
  text "10" at 101.465,33.216 h0.85 r90
  text "70" at 62.375,32.748 h0.85 r90
  text "10" at 69.758,32.426 h0.85 r90
  text "70" at 94.037,32.176 h0.85 r90
  text "20" at 101.465,28.216 h0.85 r90
  text "60" at 62.375,27.748 h0.85 r90
  text "20" at 69.758,27.426 h0.85 r90
  text "60" at 94.037,27.176 h0.85 r90
  text "30" at 101.465,23.216 h0.85 r90
  text "50" at 62.375,22.748 h0.85 r90
  text "30" at 69.758,22.426 h0.85 r90
  text "50" at 94.037,22.176 h0.85 r90
  text "40" at 101.465,18.216 h0.85 r90
  text "40" at 69.758,17.426 h0.85 r90
Mechanical 16:
  drawing of 1701 lines, arcs and shapes, not listed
